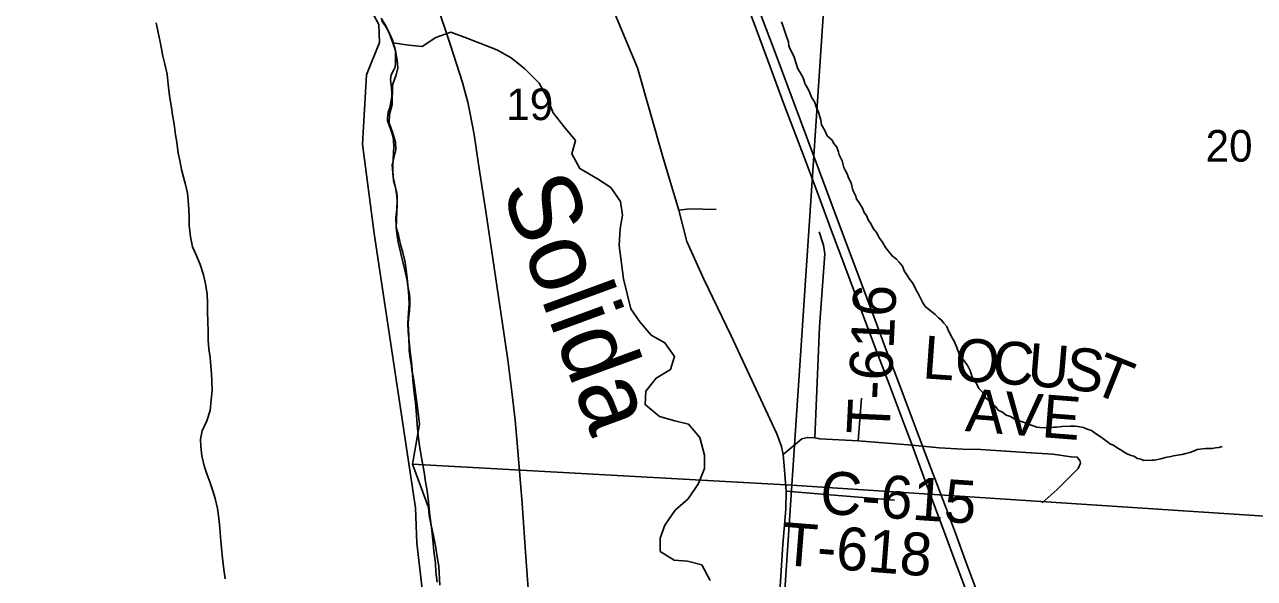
# Model space of a CAD drawing. Extents: x 0 to 45.4, y -2.2 to 22.
# Drawn here: x 2.837 to 4.467, y 17.183 to 17.917 of the extents above; entities that cross this region are included whole.
import ezdxf

# ---------------------------------------------------------------- set-up
doc = ezdxf.new("R2010")
doc.units = 0
for name, color, linetype in [('GM_X_Corporation', 7, 'Continuous'), ('GM_X_County_Road', 7, 'Continuous'), ('GM_X_County_Road_Text', 7, 'Continuous'), ('GM_X_Major_River', 7, 'Continuous'), ('GM_X_Minor_River', 7, 'Continuous'), ('GM_X_Minor_River_Text', 7, 'Continuous'), ('GM_X_Rail_Line', 7, 'Continuous'), ('GM_X_Section_Text', 7, 'Continuous'), ('GM_X_Township_Road', 7, 'Continuous'), ('GM_X_Township_Road_Text', 7, 'Continuous'), ('GM_X_US_Route', 7, 'Continuous')]:
    doc.layers.add(name, color=color, linetype=linetype)

msp = doc.modelspace()

# ---------------------------------------------------------------- linework, layer by layer
at = {"layer": 'GM_X_Corporation'}
for points in [[(2.4503, 19.1527), (2.5862, 19.0536), (2.6706, 19.0104), (2.7255, 18.9508), (2.8035, 18.8848), (2.8867, 18.8036), (3.006, 18.5933), (3.1607, 18.2624), (3.2417, 18.0381), (3.3068, 17.9167), (3.3076, 17.8928), (3.2906, 17.8503), (3.2853, 17.7584), (3.3008, 17.64), (3.3557, 17.2765), (3.3572, 17.2298), (3.3712, 17.1086)], [(2.4503, 19.1527), (2.5862, 19.0536), (2.6706, 19.0104), (2.7255, 18.9508), (2.8035, 18.8848), (2.8867, 18.8036), (3.006, 18.5933), (3.1607, 18.2624), (3.2417, 18.0381), (3.3068, 17.9167), (3.3076, 17.8928), (3.2906, 17.8503), (3.2853, 17.7584), (3.3008, 17.64), (3.3557, 17.2765), (3.3572, 17.2298), (3.3712, 17.1086)], [(3.9206, 18.2985), (3.854, 17.3067), (3.3517, 17.3343), (3.3608, 17.3873), (3.3589, 17.4025), (3.3544, 17.4358), (3.3533, 17.4453), (3.3518, 17.4529), (3.3506, 17.4582), (3.3502, 17.4643), (3.3484, 17.4749), (3.3472, 17.4851), (3.3465, 17.5044), (3.3457, 17.5207), (3.3461, 17.5264), (3.3476, 17.5378), (3.348, 17.5465), (3.348, 17.5529), (3.3477, 17.5594), (3.3454, 17.57), (3.3443, 17.5779), (3.3412, 17.5916), (3.3359, 17.6135), (3.3337, 17.6226), (3.3325, 17.6279), (3.331, 17.6367), (3.3299, 17.648), (3.3303, 17.6567), (3.3307, 17.6704), (3.3314, 17.6764), (3.3314, 17.6829), (3.3314, 17.6882), (3.3307, 17.6939), (3.3292, 17.7007), (3.3265, 17.7102), (3.3258, 17.7155), (3.3254, 17.7219), (3.3254, 17.7302), (3.3266, 17.7553), (3.3262, 17.7636), (3.3254, 17.7693), (3.3232, 17.7761), (3.3186, 17.7897), (3.3183, 17.7928), (3.319, 17.7966), (3.3194, 17.8007), (3.3213, 17.8064), (3.3228, 17.8144), (3.324, 17.8212), (3.324, 17.8257), (3.3236, 17.8333), (3.3228, 17.8394), (3.3225, 17.8439), (3.3232, 17.85), (3.3266, 17.8568), (3.3285, 17.8602), (3.3289, 17.8666), (3.3289, 17.8738), (3.3289, 17.881), (3.3282, 17.886), (3.327, 17.8901), (3.3255, 17.8951), (3.3198, 17.9079), (3.3157, 17.9148), (3.3104, 17.922)], [(3.3879, 17.174), (3.3864, 17.1994), (3.3846, 17.2089), (3.3819, 17.2263), (3.3793, 17.2396), (3.3759, 17.2555), (3.3736, 17.2665), (3.3728, 17.2771), (3.3517, 17.3343), (3.854, 17.3067), (3.7867, 16.2913)]]:
    msp.add_lwpolyline(points, dxfattribs=at)
for points in [[(3.9206, 18.2985), (5.0121, 18.2353), (4.9524, 17.2347), (3.854, 17.3067)], [(4.9524, 17.2347), (4.8941, 16.2254), (3.7867, 16.2913), (3.854, 17.3067)]]:
    msp.add_lwpolyline(points, close=True, dxfattribs=at)
at = {"layer": 'GM_X_County_Road'}
for points in [[(3.6201, 17.9303), (3.6499, 17.8596), (3.6842, 17.7385), (3.7043, 17.6708), (3.715, 17.6293), (3.7377, 17.5796), (3.7738, 17.5046), (3.8344, 17.3748), (3.8404, 17.3578), (3.8429, 17.347), (3.8442, 17.3322), (3.8468, 17.2987), (3.8462, 17.275), (3.8421, 17.2281), (3.8334, 17.0889)], [(3.8429, 17.347), (3.8673, 17.3679), (3.8749, 17.3698), (3.8845, 17.3695), (3.8913, 17.3679), (3.9422, 17.3654), (4.0136, 17.3594)]]:
    msp.add_lwpolyline(points, dxfattribs=at)
at = {"layer": 'GM_X_Major_River'}
for points in [[(3.0117, 17.9192), (3.0147, 17.9063), (3.0173, 17.8941), (3.0188, 17.8846), (3.0207, 17.8748), (3.0234, 17.8641), (3.0264, 17.8509), (3.0279, 17.838), (3.0294, 17.8224), (3.0321, 17.8068), (3.0336, 17.797), (3.0355, 17.7848), (3.0373, 17.7708), (3.0392, 17.7609), (3.0411, 17.7465), (3.0434, 17.7366), (3.0453, 17.7249), (3.0479, 17.7146), (3.0509, 17.7051), (3.0532, 17.6934), (3.0543, 17.6835), (3.0551, 17.6721), (3.0555, 17.6611), (3.0555, 17.6505), (3.0574, 17.6357), (3.06, 17.6224), (3.0645, 17.6126), (3.0702, 17.5989), (3.0744, 17.5852), (3.0774, 17.5731), (3.0793, 17.5598), (3.08, 17.548), (3.08, 17.5378), (3.0804, 17.5218), (3.0808, 17.512), (3.0808, 17.4987), (3.0815, 17.4873), (3.0834, 17.4755), (3.0845, 17.4641), (3.0853, 17.4547), (3.0857, 17.4444), (3.086, 17.4319), (3.0849, 17.4197), (3.0834, 17.4053), (3.0789, 17.392), (3.0728, 17.3784), (3.0705, 17.3674), (3.0709, 17.3579), (3.0724, 17.3453), (3.0754, 17.332), (3.0788, 17.3214), (3.083, 17.3108), (3.0868, 17.299), (3.0902, 17.2891), (3.0932, 17.2758), (3.0951, 17.2629), (3.0962, 17.25), (3.0973, 17.2375), (3.0985, 17.2231), (3.0996, 17.2098), (3.1015, 17.195), (3.1034, 17.1824)], [(3.3844, 17.1781), (3.3825, 17.1914), (3.3821, 17.2032), (3.3798, 17.2192), (3.3783, 17.234), (3.3772, 17.2469), (3.3753, 17.2602), (3.3742, 17.2708), (3.3726, 17.2845), (3.3711, 17.2989), (3.3689, 17.3111), (3.367, 17.324), (3.3628, 17.3456), (3.3606, 17.3593), (3.3591, 17.3722), (3.3579, 17.3866), (3.3564, 17.4056), (3.3553, 17.4155), (3.3538, 17.4284), (3.3519, 17.4466), (3.3511, 17.4599), (3.35, 17.4701), (3.3485, 17.4826), (3.3474, 17.4925), (3.3459, 17.5096), (3.3455, 17.5214), (3.3462, 17.535), (3.347, 17.5464), (3.3466, 17.5563), (3.3459, 17.5673), (3.3444, 17.5813), (3.3432, 17.5912), (3.3417, 17.6018), (3.3387, 17.6147), (3.3357, 17.6254), (3.333, 17.6379), (3.33, 17.6485), (3.3293, 17.6614), (3.3308, 17.672), (3.3311, 17.6838), (3.3304, 17.6933), (3.3285, 17.7028), (3.3259, 17.7145), (3.3244, 17.7305), (3.327, 17.74), (3.3293, 17.7506), (3.3289, 17.7608), (3.3247, 17.7756), (3.3206, 17.7863), (3.321, 17.7976), (3.3244, 17.8109), (3.3251, 17.8367), (3.3297, 17.85), (3.3319, 17.8595), (3.3312, 17.8697), (3.3289, 17.8819), (3.3255, 17.8925), (3.321, 17.9046), (3.3161, 17.9153), (3.31, 17.9251)]]:
    msp.add_lwpolyline(points, dxfattribs=at)
at = {"layer": 'GM_X_Minor_River'}
for points in [[(3.8406, 17.9205), (3.8421, 17.9156), (3.8457, 17.9049), (3.8471, 17.901), (3.8496, 17.8938), (3.8503, 17.8888), (3.8521, 17.8842), (3.8569, 17.8747), (3.8623, 17.8579), (3.8652, 17.8533), (3.8693, 17.8464), (3.8721, 17.8376), (3.874, 17.8341), (3.8773, 17.8284), (3.8798, 17.8215), (3.8846, 17.8134), (3.8864, 17.8077), (3.8897, 17.8008), (3.8925, 17.7901), (3.8935, 17.784), (3.898, 17.7763), (3.9012, 17.7694), (3.9072, 17.764), (3.9098, 17.759), (3.9139, 17.7544), (3.916, 17.7479), (3.9171, 17.7441), (3.9207, 17.7364), (3.9232, 17.7273), (3.9251, 17.7238), (3.9276, 17.7192), (3.9294, 17.7135), (3.9327, 17.707), (3.9352, 17.6974), (3.9392, 17.6894), (3.9399, 17.6856), (3.9429, 17.6814), (3.9477, 17.6737), (3.9502, 17.6676), (3.9535, 17.6629), (3.9553, 17.658), (3.9594, 17.6522), (3.962, 17.6468), (3.9668, 17.6407), (3.9693, 17.6349), (3.9745, 17.6284), (3.9782, 17.6215), (3.9838, 17.6149), (3.9871, 17.6103), (3.9927, 17.606), (3.9964, 17.6018), (4.0009, 17.5968), (4.003, 17.5907), (4.0075, 17.5841), (4.0104, 17.5791), (4.0141, 17.5745), (4.0163, 17.5707), (4.0196, 17.5642), (4.0218, 17.5607), (4.0244, 17.555), (4.0273, 17.5492), (4.031, 17.5434), (4.0392, 17.5365), (4.044, 17.5326), (4.0485, 17.5283), (4.0526, 17.5252), (4.0556, 17.5214), (4.0597, 17.5167), (4.0618, 17.511), (4.0666, 17.5018), (4.0692, 17.4972), (4.0728, 17.4891), (4.0761, 17.4803), (4.0827, 17.4715), (4.0861, 17.4665), (4.0883, 17.463), (4.0905, 17.4584)], [(3.3255, 17.8925), (3.3468, 17.8893), (3.3643, 17.8877), (3.3825, 17.8998), (3.4022, 17.9065), (3.4211, 17.8996), (3.4408, 17.892), (3.4634, 17.8835), (3.4823, 17.8728), (3.5005, 17.8583), (3.5193, 17.8393), (3.5298, 17.8195), (3.5381, 17.7997), (3.5524, 17.7814), (3.5675, 17.7631), (3.5628, 17.7457), (3.5734, 17.7259), (3.5968, 17.7122), (3.6142, 17.7007), (3.627, 17.6824), (3.6299, 17.6642), (3.6268, 17.6467), (3.6252, 17.6239), (3.6311, 17.5799), (3.6408, 17.5403), (3.6528, 17.5228), (3.6679, 17.5053), (3.686, 17.4953), (3.6988, 17.4771), (3.6934, 17.4596), (3.6745, 17.4483), (3.6608, 17.4309), (3.6599, 17.4134), (3.6788, 17.3974), (3.6992, 17.392), (3.7174, 17.3873), (3.7324, 17.3698), (3.7384, 17.3462), (3.7383, 17.3287), (3.7307, 17.309), (3.717, 17.2886), (3.6995, 17.2734), (3.6858, 17.2537), (3.6796, 17.2363), (3.6796, 17.2188), (3.6985, 17.2073), (3.7159, 17.2057), (3.7348, 17.2011), (3.7461, 17.1805)], [(4.0905, 17.4584), (4.093, 17.4497), (4.0985, 17.442), (4.1018, 17.4347), (4.107, 17.4297), (4.1114, 17.422), (4.1166, 17.4177), (4.1207, 17.4135), (4.1245, 17.4104), (4.1278, 17.4061), (4.1334, 17.4034), (4.1383, 17.3991), (4.1439, 17.3975), (4.1488, 17.3944), (4.1556, 17.3916), (4.1612, 17.39), (4.1699, 17.3864), (4.1752, 17.3848), (4.1789, 17.3836), (4.1827, 17.3831), (4.1891, 17.3826), (4.1941, 17.3829), (4.1975, 17.3829), (4.2016, 17.3832), (4.2051, 17.3835), (4.2123, 17.3841), (4.2229, 17.3847), (4.2293, 17.3846), (4.2331, 17.3842), (4.2407, 17.3829), (4.2455, 17.3809), (4.2512, 17.3789), (4.2568, 17.375), (4.2643, 17.3703), (4.2695, 17.3661), (4.2763, 17.361), (4.2804, 17.3594), (4.2853, 17.3559), (4.2916, 17.3524), (4.2961, 17.3496), (4.2995, 17.3477), (4.304, 17.3457), (4.3074, 17.3449), (4.3123, 17.3421), (4.3168, 17.3409), (4.3206, 17.3393), (4.3312, 17.3395), (4.3346, 17.3399), (4.3433, 17.3416), (4.3494, 17.3434), (4.3566, 17.3444), (4.3601, 17.3455), (4.3654, 17.3462), (4.3715, 17.3472), (4.3764, 17.3486), (4.3817, 17.3497), (4.3867, 17.3515), (4.3913, 17.3537), (4.3951, 17.3544), (4.4027, 17.355), (4.4061, 17.355), (4.4114, 17.3553), (4.4156, 17.356), (4.4201, 17.3566), (4.4243, 17.3577)]]:
    msp.add_lwpolyline(points, dxfattribs=at)
at = {"layer": 'GM_X_Rail_Line'}
msp.add_lwpolyline([(3.5067, 17.1453), (3.5018, 17.2117), (3.4968, 17.2824), (3.4908, 17.3575), (3.4876, 17.3927), (3.4838, 17.4265), (3.4779, 17.4725), (3.4655, 17.556), (3.4562, 17.6187), (3.4488, 17.669), (3.4392, 17.7318), (3.4331, 17.7712), (3.4277, 17.8007), (3.4248, 17.8139), (3.4215, 17.8266), (3.4177, 17.84), (3.4133, 17.8539), (3.4019, 17.8893), (3.3818, 17.9486)], dxfattribs=at)
at = {"layer": 'GM_X_Township_Road'}
for p, q in [((3.9422, 17.3654), (3.9465, 17.422)), ((3.8468, 17.2987), (3.9901, 17.2869))]:
    msp.add_line(p, q, dxfattribs=at)
for points in [[(3.7043, 17.6708), (3.7184, 17.6726), (3.7541, 17.6719)], [(3.8845, 17.3695), (3.8909, 17.5165), (3.8978, 17.613), (3.896, 17.6245), (3.8905, 17.6423)], [(4.0136, 17.3594), (4.0274, 17.3582), (4.0496, 17.3562), (4.0806, 17.3544), (4.1046, 17.354), (4.1645, 17.3498), (4.2003, 17.3477), (4.2244, 17.3443), (4.2324, 17.3436), (4.2359, 17.3394), (4.2368, 17.3357), (4.2336, 17.3287), (4.206, 17.301), (4.186, 17.2832)]]:
    msp.add_lwpolyline(points, dxfattribs=at)
at = {"layer": 'GM_X_US_Route'}
for points in [[(3.6559, 18.2316), (3.6681, 18.2121), (3.692, 18.1695), (3.7086, 18.1377), (3.7227, 18.1111), (3.7352, 18.0846), (3.7461, 18.0624), (3.7573, 18.0361), (3.7693, 18.0094), (3.7859, 17.9667), (3.8017, 17.9252), (3.8218, 17.8703), (3.844, 17.8104), (3.8705, 17.741), (3.8889, 17.6918), (3.9068, 17.6433), (3.9256, 17.5933), (3.9474, 17.535), (3.965, 17.4877), (3.9833, 17.4403), (4.0032, 17.3873)], [(3.7977, 17.9707), (3.832, 17.8799), (3.9175, 17.6509), (3.9604, 17.5371), (3.9798, 17.4844), (3.9978, 17.4374), (4.0274, 17.3582), (4.0577, 17.2782), (4.0709, 17.2431), (4.0849, 17.2051), (4.0994, 17.1661)], [(4.0032, 17.3873), (4.0136, 17.3594), (4.0311, 17.3124), (4.0584, 17.2389), (4.0707, 17.2055), (4.0902, 17.154)]]:
    msp.add_lwpolyline(points, dxfattribs=at)

# ---------------------------------------------------------------- texts
at = {"layer": 'GM_X_County_Road_Text'}
msp.add_text('C-615', height=0.05682, rotation=356.1656, dxfattribs=at).set_placement((3.8904, 17.2691))
at = {"layer": 'GM_X_Minor_River_Text'}
for s, height, rotation, p in [('Lick', 0.0947, 348.6135, (4.3978, 17.9454)), ('Solida', 0.09473, 290.1019, (3.4686, 17.699))]:
    msp.add_text(s, height=height, rotation=rotation, dxfattribs=at).set_placement(p)
at = {"layer": 'GM_X_Section_Text'}
for s, p in [('19', (3.4758, 17.7902)), ('20', (4.4025, 17.7352))]:
    msp.add_text(s, height=0.04186, rotation=0, dxfattribs=at).set_placement(p)
at = {"layer": 'GM_X_Township_Road_Text'}
for s, height, rotation, p in [('T-616', 0.05682, 87.2565, (3.9835, 17.3726)), ('L', 0.0568, 355.951, (4.0263, 17.4483)), ('O', 0.0568, 355.9508, (4.0687, 17.4453)), ('C', 0.0568, 355.9506, (4.1186, 17.4418)), ('U', 0.0568, 355.2079, (4.1649, 17.4385)), ('S', 0.0568, 352.7483, (4.2141, 17.4344)), ('T', 0.0568, 338.228, (4.2485, 17.4305)), ('AVE', 0.05682, 355.4831, (4.0831, 17.3783)), ('T-618', 0.05682, 355.5153, (3.8398, 17.201))]:
    msp.add_text(s, height=height, rotation=rotation, dxfattribs=at).set_placement(p)

doc.saveas('drawing.dxf')
